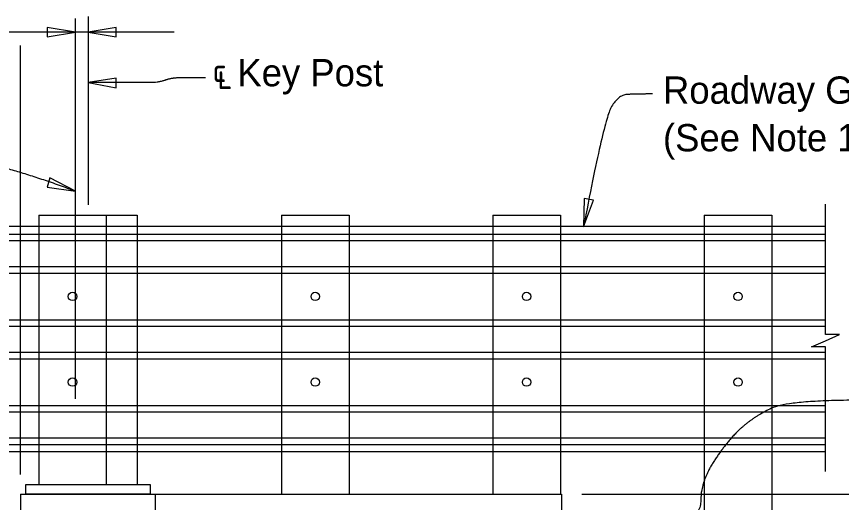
# Model space of a CAD drawing. Extents: x 21526.6 to 21595.9, y 56114.9 to 56157.2.
# Drawn here: x 21535.7 to 21541.8, y 56135.15 to 56138.74 of the extents above; entities that cross this region are included whole.
import ezdxf

# ---------------------------------------------------------------- set-up
doc = ezdxf.new("R2010")
doc.units = 0
for name, color, linetype in [('AdhocPoint_dp', 7, 'Continuous'), ('Border', 7, 'Continuous'), ('Patterning', 7, 'Continuous'), ('PlotBorder_dp', 7, 'Continuous'), ('SheetBorder_dp', 7, 'Continuous'), ('SubStrConc', 7, 'Continuous')]:
    doc.layers.add(name, color=color, linetype=linetype)

msp = doc.modelspace()

# ---------------------------------------------------------------- linework, layer by layer
at = {"layer": 'AdhocPoint_dp'}
for q in [(21535.7321, 56132.6054), (21536.7321, 56135.2101)]:
    msp.add_line((21535.7321, 56135.2101), q, dxfattribs=at)
at = {"layer": 'Patterning'}
for p, q in [((21536.1385, 56135.9162), (21536.1385, 56138.7274)), ((21536.2322, 56138.7421), (21536.2322, 56137.3509)), ((21535.8675, 56137.2726), (21536.5967, 56137.2726)), ((21535.8675, 56137.2726), (21535.8675, 56135.283)), ((21536.3675, 56137.2726), (21536.3675, 56135.283)), ((21537.6617, 56137.2725), (21537.6617, 56135.21)), ((21537.6617, 56137.2725), (21538.1617, 56137.2725)), ((21538.1617, 56137.2725), (21538.1617, 56135.21)), ((21539.2242, 56137.2725), (21539.2242, 56135.21)), ((21539.2242, 56137.2725), (21539.7242, 56137.2725)), ((21539.7242, 56137.2725), (21539.7242, 56135.21)), ((21540.7867, 56137.2725), (21540.7867, 56134.4601)), ((21540.7867, 56137.2725), (21541.2867, 56137.2725)), ((21541.2867, 56137.2725), (21541.2867, 56134.4601)), ((21534.1592, 56137.1336), (21541.6829, 56137.1336)), ((21534.1592, 56137.0854), (21541.6829, 56137.0854)), ((21534.1592, 56136.8926), (21541.6829, 56136.8926)), ((21534.1592, 56136.8444), (21541.6829, 56136.8444)), ((21534.1592, 56136.5004), (21541.6829, 56136.5004)), ((21534.1592, 56136.4522), (21541.6829, 56136.4522)), ((21534.1592, 56136.2594), (21541.6829, 56136.2594)), ((21534.1592, 56136.2112), (21541.6829, 56136.2112)), ((21534.1592, 56135.8673), (21541.6829, 56135.8673)), ((21534.1592, 56135.8191), (21541.6829, 56135.8191)), ((21534.1592, 56135.6262), (21541.6829, 56135.6262)), ((21534.1592, 56135.578), (21541.6829, 56135.578))]:
    msp.add_line(p, q, dxfattribs=at)
for centre in [(21536.1175, 56136.6725), (21536.1175, 56136.0393)]:
    msp.add_circle(centre, 0.0312, dxfattribs=at)
at = {"layer": 'PlotBorder_dp'}
for p, q in [((21536.8702, 56138.6267), (21533.9069, 56138.6267)), ((21535.7322, 56135.3555), (21535.7322, 56138.5276)), ((21539.8821, 56135.2101), (21543.3608, 56135.2101))]:
    msp.add_line(p, q, dxfattribs=at)
for points in [[(21536.1385, 56138.6267), (21535.9302, 56138.662), (21535.9302, 56138.5914)], [(21536.2322, 56138.6267), (21536.4405, 56138.5914), (21536.4405, 56138.662)], [(21536.2321, 56138.2534), (21536.44, 56138.2159), (21536.4408, 56138.2864)], [(21536.1385, 56137.4512), (21535.9508, 56137.5481), (21535.9294, 56137.4808)], [(21539.8946, 56137.1866), (21539.9683, 56137.3845), (21539.899, 56137.3977)]]:
    msp.add_lwpolyline(points, close=True, dxfattribs=at)
msp.add_lwpolyline([(21541.6829, 56135.3777), (21541.6829, 56136.3003), (21541.5795, 56136.3003), (21541.6829, 56136.3453), (21541.7862, 56136.3903), (21541.6829, 56136.3903), (21541.6829, 56137.3551)], dxfattribs=at)
for points in [[(21537.1016, 56138.2883), (21536.9673, 56138.2883), (21536.8507, 56138.2883), (21536.7517, 56138.253), (21536.6457, 56138.253), (21536.2321, 56138.2534)], [(21540.4034, 56138.1693), (21540.2833, 56138.1693), (21540.1525, 56138.1622), (21540.0465, 56137.9819), (21539.8946, 56137.1866)], [(21534.2964, 56137.7285), (21534.7211, 56137.7301), (21535.4789, 56137.6995), (21536.1385, 56137.4512)], [(21542.0754, 56135.9047), (21541.4139, 56135.9116), (21541.1398, 56135.7744), (21540.9568, 56135.6032), (21540.7613, 56135.3058), (21540.7613, 56135.0162), (21540.2137, 56134.8128), (21539.7444, 56134.8049)]]:
    msp.add_open_spline(points, degree=2, dxfattribs=at)
at = {"layer": 'SheetBorder_dp'}
for p, q in [((21536.0134, 56137.2726), (21536.0967, 56137.2726)), ((21536.5967, 56137.2726), (21536.5967, 56135.283)), ((21541.6829, 56137.1892), (21534.1592, 56137.1892)), ((21541.6829, 56135.5225), (21534.1592, 56135.5225))]:
    msp.add_line(p, q, dxfattribs=at)
msp.add_lwpolyline([(21535.7738, 56135.2101), (21535.7738, 56135.283), (21536.6905, 56135.283), (21536.6905, 56135.2101)], close=True, dxfattribs=at)
for centre in [(21537.9117, 56136.6724), (21539.4742, 56136.6724), (21541.0367, 56136.6724), (21537.9117, 56136.0393), (21539.4742, 56136.0393), (21541.0367, 56136.0393)]:
    msp.add_circle(centre, 0.0312, dxfattribs=at)
at = {"layer": 'SubStrConc'}
for p, q in [((21536.7321, 56134.46), (21536.7321, 56135.2101)), ((21536.7321, 56135.2101), (21539.7321, 56135.2101)), ((21536.7321, 56135.2101), (21539.7321, 56135.2101)), ((21539.7321, 56135.2101), (21539.7321, 56134.46))]:
    msp.add_line(p, q, dxfattribs=at)

# ---------------------------------------------------------------- texts
at = {"layer": 'Border'}
msp.add_text('℄ Key Post', height=0.2016, dxfattribs=at).set_placement((21537.1518, 56138.2259))
at = {"layer": 'PlotBorder_dp'}
for s, p in [('Roadway Guardrail Transition', (21540.4819, 56138.0972)), ('(See Note 1, Sheet 1)', (21540.4819, 56137.7452))]:
    msp.add_text(s, height=0.2016, dxfattribs=at).set_placement(p)

doc.saveas('drawing.dxf')
